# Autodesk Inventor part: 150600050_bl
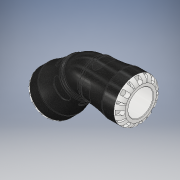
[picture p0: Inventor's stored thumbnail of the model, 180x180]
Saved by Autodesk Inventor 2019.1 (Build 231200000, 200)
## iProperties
Created: 2016-12
Part Number: 150600050_bl
Material: PVC-Piping
Description: PLASSON G-PLASS 45°  ELBOW 50-50
Document SubType Name: Modeling
Designer: KIM
Mass: 664.223 g
Surface Area: 733.008 cm^2
Volume: 474.445 cm^3
Density: 1.4 g/cm^3
Appearance: Black Cast
Author: KIM
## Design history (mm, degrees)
derived "150600.ipt"
feature "Solid1::150600.ipt" dims "ScaleForDerivedMember" = 10
tag "TaggingFeature1"
body "Solid1"
other parameters: "d1" = 34.86 [user parameter], "d3" = 62.5 [user parameter], "d4" = 85 [user parameter], "d8" = 72.25 [user parameter], "d13" = 9 [user parameter], "d14" = 9 [user parameter], "d15" = 0 [user parameter], "d17" = 360 deg [user parameter], "d19" = 8 deg [user parameter], "d20" = 1 [user parameter], "d21" = 1 [user parameter], "d22" = 8 deg [user parameter], "d24" = 0 [user parameter], "d26" = 360 deg [user parameter], "d33" = 8.5 [user parameter], "d43" = 66.3 [user parameter], "d51" = 0.85 [user parameter], "d54" = 17.5 [user parameter], "d55" = 11 [user parameter], "d57" = 17.64 [user parameter], "d58" = 0 [user parameter], "d74" = 0 [user parameter], "d77" = 4.16667 [user parameter], "d78" = 83 [user parameter], "d82" = 1 [user parameter], "d115" = 360 deg [user parameter], "d207" = 90 deg [user parameter], "d228" = 14.875 [user parameter], "d247" = 1.7 [user parameter], "d248" = 4.98 [user parameter], "d268" = 15.1725 [user parameter], "d269" = 4.55175 [user parameter], "d270" = 104 [user parameter], "d277" = 135 deg [user parameter], "d279" = 4.55175 [user parameter], "d280" = 135 deg [user parameter], "d281" = 0 [user parameter], "d282" = 0 [user parameter], "E_" = 85 [user parameter], "l_" = 83 [user parameter], "A_" = 104 [user parameter], "d9" = 11.25 [user parameter], "d11" = 85 [user parameter], "d12" = 62.5 [user parameter]
